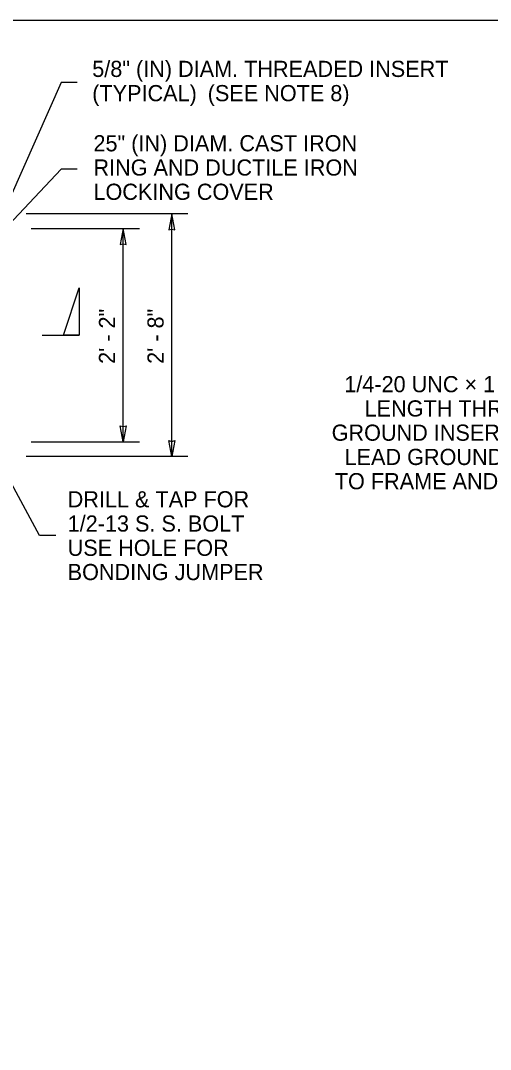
# Model space of a CAD drawing. Extents: x 99862 to 103151, y 100000 to 105076.
# Drawn here: x 100555 to 101020, y 101057 to 102076 of the extents above; entities that cross this region are included whole.
import ezdxf

# ---------------------------------------------------------------- set-up
doc = ezdxf.new("R2010")
doc.units = 0
for name, color, linetype in [('Level 1', 7, 'Continuous'), ('Level 15', 7, 'Continuous'), ('Level 20', 7, 'Continuous')]:
    doc.layers.add(name, color=color, linetype=linetype)

msp = doc.modelspace()

# ---------------------------------------------------------------- linework, layer by layer
at = {"layer": 'Level 1'}
msp.add_lwpolyline([(99862, 99999.5), (103151, 99999.5), (103151, 102075.5), (99862, 102075.5)], close=True, dxfattribs=at)
at = {"layer": 'Level 15'}
for p, q in [((100595.1, 102014.2), (100531.9, 101871.9)), ((100611.1, 102014.2), (100595.1, 102014.2)), ((100595.1, 101928.5), (100468.4, 101794.2)), ((100611.1, 101928.5), (100595.1, 101928.5)), ((100720.5, 101884.2), (100560.5, 101884.2)), ((100704.5, 101644.2), (100704.5, 101884.2)), ((100565.5, 101869.6), (100672.5, 101869.6)), ((100656.5, 101658.7), (100656.5, 101869.6)), ((100573.9, 101566.1), (100467.1, 101762.3)), ((100565.5, 101658.7), (100672.5, 101658.7)), ((100720.5, 101644.2), (100560.5, 101644.2)), ((100589.9, 101566.1), (100573.9, 101566.1))]:
    msp.add_line(p, q, dxfattribs=at)
for points in [[(100704.5, 101884.2), (100701.5, 101868.4), (100704.5, 101869.2), (100707.6, 101868.4)], [(100656.5, 101869.6), (100653.5, 101853.9), (100656.5, 101854.6), (100659.6, 101853.9)], [(100656.5, 101658.7), (100653.5, 101674.4), (100656.5, 101673.7), (100659.6, 101674.4)], [(100704.5, 101644.2), (100701.5, 101659.9), (100704.5, 101659.1), (100707.6, 101659.9)]]:
    msp.add_lwpolyline(points, close=True, dxfattribs=at)
at = {"layer": 'Level 20'}
msp.add_line((100576.5, 101764.2), (100613.1, 101764.2), dxfattribs=at)
msp.add_lwpolyline([(100597.5, 101764.2), (100613.1, 101811), (100613.1, 101764.2)], close=True, dxfattribs=at)

# ---------------------------------------------------------------- texts
for s, p in [('5/8" (IN) DIAM. THREADED INSERT', (100625.9, 102019.7)), ('(TYPICAL) ', (100625.9, 101995.7)), ('(SEE NOTE 8)', (100740.1, 101995.7)), ('1/4-20 UNC × 1 11/16" (IN) MIN.', (100875.2, 101707.7)), ('LENGTH THREADED BRASS', (100895.3, 101683.7)), ('GROUND INSERT  WITH STEEL', (100862.7, 101659.7)), ('LEAD GROUND ROD BONDED', (100875.5, 101635.7)), ('TO FRAME AND REINFORCING', (100865.8, 101611.7)), ('DRILL & TAP FOR', (100601.6, 101593.8)), ('1/2-13 S. S. BOLT', (100601.6, 101569.8)), ('USE HOLE FOR', (100601.6, 101545.8)), ('BONDING JUMPER', (100601.6, 101521.8))]:
    msp.add_text(s, height=16, dxfattribs=at).set_placement(p)
for s, rotation, p in [('25" (IN) DIAM. CAST IRON', 360, (100627.1, 101946.1)), ('RING AND DUCTILE IRON', 360, (100627.1, 101922.1)), ('LOCKING COVER', 360, (100627.1, 101898.1)), ('2\' - 2"', 90, (100648.5, 101735.8)), ('2\' - 8"', 90, (100696.5, 101735.8))]:
    msp.add_text(s, height=16, rotation=rotation, dxfattribs=at).set_placement(p)

doc.saveas('drawing.dxf')
